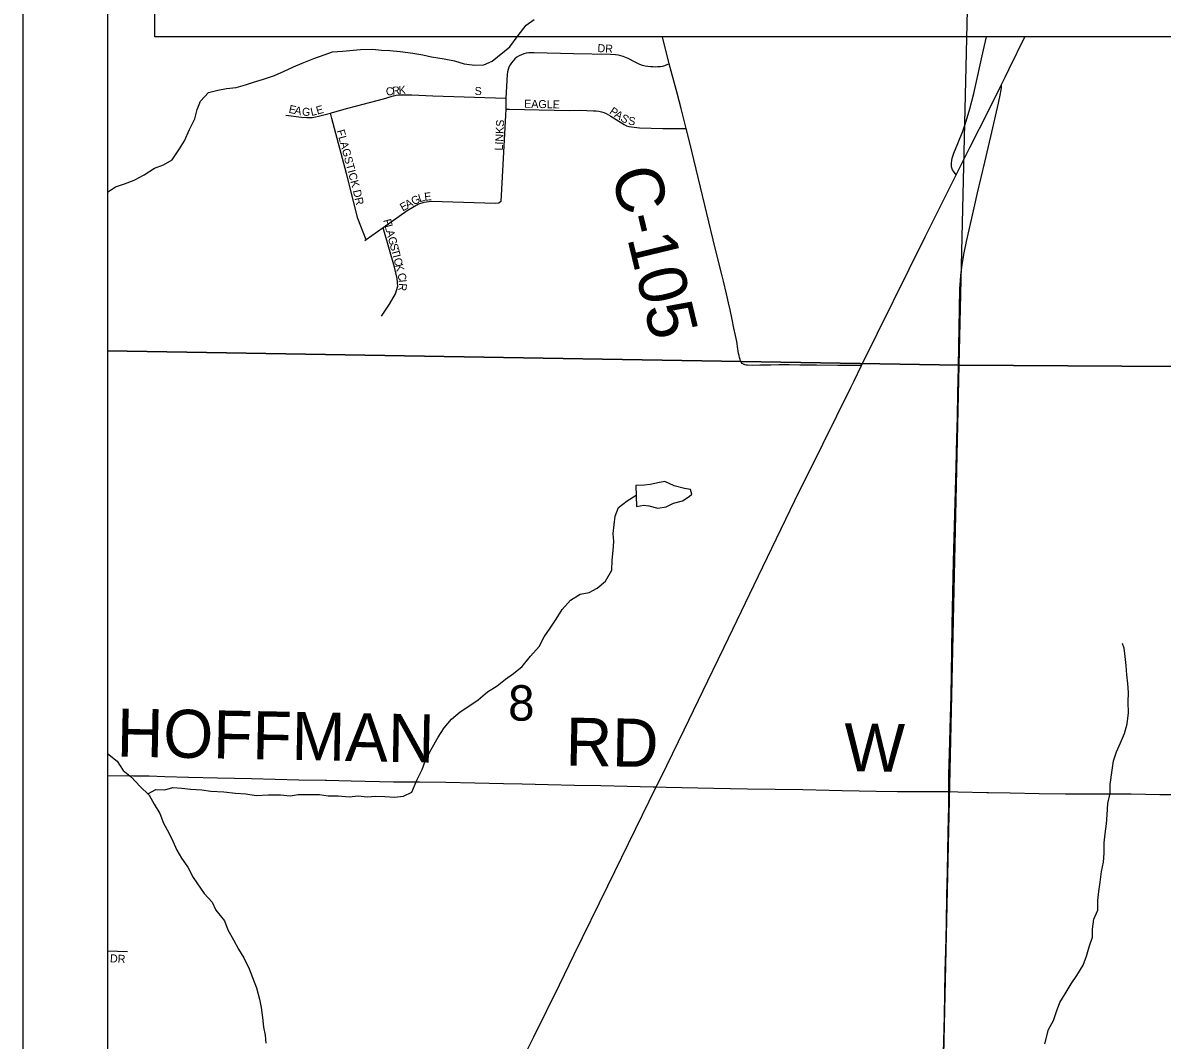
# Model space of a CAD drawing. Extents: x -97 to 34, y -21 to 22.
# Drawn here: x 3.451 to 4.799, y 15.667 to 16.869 of the extents above; entities that cross this region are included whole.
import ezdxf

# ---------------------------------------------------------------- set-up
doc = ezdxf.new("R2010")
doc.units = 0
for name, color, linetype in [('GM_X_County_Road', 7, 'Continuous'), ('GM_X_County_Road_Text', 7, 'Continuous'), ('GM_X_Minor_Lake', 7, 'Continuous'), ('GM_X_Minor_River', 7, 'Continuous'), ('GM_X_Section', 7, 'Continuous'), ('GM_X_Section_Text', 7, 'Continuous'), ('GM_X_State_Route', 7, 'Continuous'), ('GM_X_Township_Subdivision', 7, 'Continuous'), ('GM_X_Township_Subdivision_Text', 7, 'Continuous'), ('SH_Data', 7, 'Continuous'), ('SH_Text', 7, 'Continuous')]:
    doc.layers.add(name, color=color, linetype=linetype)

msp = doc.modelspace()

# ---------------------------------------------------------------- linework, layer by layer
at = {"layer": 'GM_X_County_Road'}
for points in [[(4.2162, 16.821), (4.2085, 16.8511), (4.208, 16.8527)], [(4.5557, 16.6897), (4.5525, 16.694), (4.5514, 16.6957), (4.5506, 16.6978), (4.5502, 16.6991), (4.55, 16.7006), (4.5499, 16.7021), (4.5499, 16.7036), (4.5503, 16.7065), (4.551, 16.7094), (4.5529, 16.7152), (4.5576, 16.7267), (4.5635, 16.7412), (4.5676, 16.753), (4.5719, 16.7679), (4.5764, 16.786), (4.5881, 16.8375), (4.5915, 16.8527)], [(4.2363, 16.7446), (4.2304, 16.7683), (4.2256, 16.7862), (4.2162, 16.821)], [(4.5576, 16.4315), (4.5584, 16.4622), (4.5587, 16.4871), (4.5596, 16.5306), (4.5601, 16.5554), (4.5606, 16.5648), (4.5611, 16.571), (4.5627, 16.5834), (4.5648, 16.5956), (4.5679, 16.6109), (4.5761, 16.6473), (4.5808, 16.6685), (4.5894, 16.7048), (4.5966, 16.735), (4.6055, 16.7744), (4.6082, 16.7858), (4.6086, 16.7882), (4.6089, 16.7901), (4.6091, 16.7925), (4.6092, 16.7964)], [(4.2789, 16.5703), (4.2704, 16.6029), (4.2531, 16.6752), (4.2401, 16.7293), (4.2363, 16.7446)], [(4.4438, 16.4643), (4.4385, 16.4642), (4.4323, 16.4641), (4.423, 16.4643), (4.4156, 16.4643), (4.3904, 16.4646), (4.3706, 16.4648), (4.3581, 16.465), (4.3457, 16.4649), (4.3365, 16.4648), (4.3274, 16.4647), (4.3235, 16.4646), (4.3147, 16.4643), (4.3087, 16.4645), (4.3071, 16.4647), (4.3055, 16.465), (4.3039, 16.4658), (4.3026, 16.4667), (4.3014, 16.4681), (4.3005, 16.4698), (4.2999, 16.4715), (4.2992, 16.4737), (4.2988, 16.4762), (4.2983, 16.4785), (4.2979, 16.4811), (4.2975, 16.484), (4.296, 16.4928), (4.2946, 16.4998), (4.2927, 16.5086), (4.2906, 16.5185), (4.2882, 16.5301), (4.2863, 16.5385), (4.2841, 16.5491), (4.2805, 16.5639), (4.2789, 16.5703)], [(4.547, 15.9605), (4.5471, 15.9807), (4.5476, 16.0056), (4.5489, 16.0491), (4.5496, 16.0739), (4.5505, 16.1267), (4.5507, 16.1578), (4.5517, 16.1951), (4.5526, 16.2324), (4.5557, 16.3442), (4.5565, 16.3783), (4.557, 16.4032), (4.5576, 16.4312), (4.5576, 16.4315)], [(3.5515, 15.9797), (3.5824, 15.9793)], [(3.5824, 15.9793), (3.601, 15.9791), (3.6196, 15.9785), (3.6476, 15.9776), (3.6817, 15.977), (3.7221, 15.9759), (3.7501, 15.9753), (3.778, 15.9746), (3.8091, 15.974), (3.8106, 15.974)], [(3.8106, 15.974), (3.8401, 15.9733), (3.8898, 15.9721), (3.9209, 15.972), (3.952, 15.9717), (3.9861, 15.971), (4.0202, 15.9702), (4.042, 15.9696), (4.0731, 15.969), (4.1041, 15.9683), (4.1352, 15.9676), (4.1663, 15.9669), (4.1973, 15.9663), (4.2009, 15.9662)], [(4.2009, 15.9662), (4.2127, 15.9657), (4.2313, 15.9652), (4.2686, 15.9645), (4.3089, 15.9639), (4.3741, 15.9629), (4.4052, 15.9623), (4.4207, 15.962), (4.4611, 15.9611), (4.486, 15.9606), (4.5388, 15.9608), (4.547, 15.9605)], [(4.5335, 15.2947), (4.5335, 15.2973), (4.5339, 15.3284), (4.5342, 15.3594), (4.5352, 15.3998), (4.5356, 15.4278), (4.5359, 15.4495), (4.5369, 15.493), (4.5379, 15.5396), (4.5394, 15.5986), (4.5405, 15.6514), (4.5417, 15.695), (4.5426, 15.7478), (4.5432, 15.7726), (4.5441, 15.8037), (4.5446, 15.8379), (4.5452, 15.8658), (4.546, 15.9124), (4.5468, 15.9435), (4.547, 15.959), (4.547, 15.9605)], [(4.547, 15.9605), (4.5575, 15.9601), (4.5917, 15.9595), (4.594, 15.9594)], [(4.594, 15.9594), (4.6195, 15.9589), (4.6537, 15.9584), (4.6851, 15.958), (4.7283, 15.9579), (4.7625, 15.9577), (4.7967, 15.9573), (4.8246, 15.957), (4.8495, 15.9569), (4.8619, 15.9569), (4.9054, 15.9566), (4.9458, 15.9566), (4.9862, 15.9567), (5.0235, 15.9568), (5.0577, 15.9568), (5.0918, 15.9568), (5.1291, 15.9569), (5.2006, 15.9563), (5.2565, 15.9559), (5.285, 15.9558)]]:
    msp.add_lwpolyline(points, dxfattribs=at)
at = {"layer": 'GM_X_Minor_Lake'}
for points in [[(4.1774, 16.2974), (4.1861, 16.2992), (4.1921, 16.2983), (4.2027, 16.2955), (4.2125, 16.2972), (4.2213, 16.3016), (4.2319, 16.3044), (4.2396, 16.3096), (4.243, 16.3122), (4.2412, 16.3175), (4.2341, 16.3188), (4.222, 16.322), (4.2111, 16.3272), (4.2047, 16.3261), (4.1937, 16.3237), (4.1869, 16.323), (4.1767, 16.3224)], [(4.1767, 16.3224), (4.1774, 16.2974)]]:
    msp.add_lwpolyline(points, dxfattribs=at)
at = {"layer": 'GM_X_Minor_River'}
for points in [[(3.5515, 16.6693), (3.561, 16.6754), (3.5716, 16.679), (3.5834, 16.6833), (3.5952, 16.6899), (3.6071, 16.6977), (3.6181, 16.7017), (3.628, 16.7076), (3.6369, 16.7203), (3.6428, 16.7301), (3.6487, 16.7432), (3.6549, 16.756), (3.6577, 16.767), (3.6617, 16.7768), (3.6713, 16.7872), (3.6823, 16.79), (3.6926, 16.7918), (3.7039, 16.7931), (3.7149, 16.7963), (3.7244, 16.7992), (3.7362, 16.8028), (3.7491, 16.8071), (3.7606, 16.8122), (3.7716, 16.8173), (3.7819, 16.8217), (3.7956, 16.8271), (3.8078, 16.8315), (3.818, 16.8351), (3.8298, 16.836), (3.851, 16.8379), (3.865, 16.8381), (3.8759, 16.8371), (3.8857, 16.8366), (3.8978, 16.8356), (3.9129, 16.8335), (3.9246, 16.8314), (3.9351, 16.8293), (3.9498, 16.8268), (3.9623, 16.8246), (3.9736, 16.821), (3.9864, 16.8193), (3.997, 16.8199), (4.0069, 16.8239), (4.0276, 16.841), (4.0373, 16.8544), (4.0469, 16.8668), (4.0565, 16.8734)], [(3.5992, 15.958), (3.6089, 15.963), (3.6195, 15.9628), (3.629, 15.9653), (3.6396, 15.9644), (3.6497, 15.9634), (3.6633, 15.9628), (3.6739, 15.9611), (3.6894, 15.9601), (3.703, 15.9587), (3.7154, 15.9578), (3.7275, 15.956), (3.7423, 15.9569), (3.7562, 15.9567), (3.7676, 15.9557), (3.7774, 15.9571), (3.7903, 15.9572), (3.8024, 15.957), (3.8126, 15.9557), (3.8247, 15.9555), (3.8375, 15.9545), (3.8481, 15.9555), (3.8587, 15.9545), (3.8689, 15.9551), (3.8798, 15.9549), (3.8912, 15.954), (3.9018, 15.9553), (3.9117, 15.9597), (3.9176, 15.974), (3.9238, 15.9868), (3.9274, 15.9966), (3.9344, 16.0105), (3.943, 16.0247), (3.95, 16.036), (3.9585, 16.0461), (3.9688, 16.055), (3.9791, 16.0616), (3.9902, 16.069), (4.0013, 16.0783), (4.0128, 16.0857), (4.0224, 16.0935), (4.032, 16.1001), (4.0423, 16.1083), (4.052, 16.1206), (4.0624, 16.1322), (4.0682, 16.1435), (4.0752, 16.1536), (4.0825, 16.1645), (4.0895, 16.1757), (4.0992, 16.1869), (4.111, 16.1939), (4.1213, 16.196), (4.1308, 16.2012), (4.1408, 16.2093), (4.1482, 16.2225), (4.1487, 16.2342), (4.1497, 16.2456), (4.1506, 16.2562), (4.15, 16.2657), (4.1509, 16.2759), (4.1522, 16.2861), (4.1562, 16.2963), (4.1665, 16.3044), (4.177, 16.3108)], [(4.6606, 15.6625), (4.665, 15.6794), (4.6709, 15.6899), (4.6741, 15.7005), (4.6784, 15.711), (4.6846, 15.7215), (4.6916, 15.7332), (4.6982, 15.7433), (4.706, 15.7553), (4.7099, 15.7658), (4.7131, 15.7772), (4.7167, 15.7885), (4.7169, 15.7979), (4.7186, 15.8097), (4.7233, 15.8202), (4.7231, 15.8319), (4.7244, 15.8425), (4.7261, 15.8535), (4.7275, 15.866), (4.7299, 15.8773), (4.7305, 15.8879), (4.7307, 15.9001), (4.732, 15.9106), (4.7333, 15.9224), (4.7343, 15.933), (4.7352, 15.9466), (4.7377, 15.9587), (4.7379, 15.9689), (4.7401, 15.9859), (4.7417, 15.9969), (4.7453, 16.0075), (4.75, 16.018), (4.7548, 16.0293), (4.758, 16.0406), (4.7593, 16.0535), (4.7592, 16.0664), (4.7593, 16.0777), (4.7588, 16.0883), (4.7574, 16.0986), (4.7565, 16.1096), (4.7555, 16.1202), (4.7545, 16.1301), (4.7524, 16.1355)], [(3.5515, 16.0061), (3.5518, 16.0057), (3.563, 15.9964), (3.5703, 15.9853), (3.58, 15.9775), (3.5901, 15.9671), (3.6009, 15.9563), (3.6067, 15.9456), (3.6137, 15.9345), (3.6181, 15.9234), (3.6243, 15.9116), (3.6291, 15.902), (3.6338, 15.8913), (3.6393, 15.8817), (3.6467, 15.871), (3.6529, 15.8591), (3.6662, 15.84), (3.6755, 15.8299), (3.6799, 15.8204), (3.6899, 15.8077), (3.6939, 15.797), (3.7009, 15.7852), (3.7067, 15.7741), (3.713, 15.7641), (3.7192, 15.7511), (3.7232, 15.7408), (3.7279, 15.7286), (3.7314, 15.7153), (3.7336, 15.7054), (3.7349, 15.6936), (3.7362, 15.6822), (3.7383, 15.6727), (3.7389, 15.6632)]]:
    msp.add_lwpolyline(points, dxfattribs=at)
at = {"layer": 'GM_X_Section'}
for p, q in [((3.5515, 17.0296), (3.5515, 16.4817)), ((3.5515, 16.4817), (3.5515, 15.4711))]:
    msp.add_line(p, q, dxfattribs=at)
for points in [[(3.5515, 16.4817), (4.5591, 16.4647), (4.5827, 17.473), (3.5795, 17.4795), (3.5515, 17.0296)], [(3.5515, 15.4711), (4.5367, 15.4537), (4.5591, 16.4647), (3.5515, 16.4817)]]:
    msp.add_lwpolyline(points, dxfattribs=at)
for points in [[(4.5827, 17.473), (5.5851, 17.4654), (5.5865, 16.4584), (4.5591, 16.4647)], [(4.5591, 16.4647), (5.5865, 16.4584), (5.5758, 15.4541), (4.5367, 15.4537)]]:
    msp.add_lwpolyline(points, close=True, dxfattribs=at)
at = {"layer": 'GM_X_State_Route'}
for points in [[(4.6184, 16.8152), (4.6369, 16.8527)], [(4.4345, 16.4455), (4.4438, 16.4643), (4.5189, 16.6165), (4.5557, 16.6897), (4.5719, 16.722), (4.5943, 16.7663), (4.6092, 16.7964), (4.6135, 16.8053), (4.6184, 16.8152)], [(4.0339, 15.6263), (4.0561, 15.6707), (4.0862, 15.7321), (4.1039, 15.7681), (4.1437, 15.8492), (4.1764, 15.9162), (4.2009, 15.9662), (4.2065, 15.9776), (4.2337, 16.0334), (4.262, 16.0916), (4.274, 16.1167), (4.281, 16.1313), (4.327, 16.2263), (4.3649, 16.3046), (4.398, 16.3714), (4.4309, 16.4382), (4.4345, 16.4455)]]:
    msp.add_lwpolyline(points, dxfattribs=at)
at = {"layer": 'GM_X_Township_Subdivision'}
for points in [[(4.2162, 16.821), (4.2107, 16.8186), (4.2082, 16.8179), (4.2057, 16.8175), (4.2028, 16.8172), (4.2002, 16.8171), (4.197, 16.8172), (4.1939, 16.8175), (4.1907, 16.8178), (4.1876, 16.8183), (4.1845, 16.8191), (4.1815, 16.8201), (4.1757, 16.8228), (4.1674, 16.8271), (4.1617, 16.8295), (4.1588, 16.8305), (4.1558, 16.8311), (4.1528, 16.8316), (4.1467, 16.832), (4.1031, 16.8327), (4.0562, 16.8341), (4.0501, 16.8339), (4.0471, 16.8335), (4.0441, 16.8327), (4.0413, 16.8317), (4.0386, 16.8303), (4.036, 16.8287), (4.0337, 16.8268), (4.0316, 16.8246), (4.0297, 16.8222), (4.028, 16.8197), (4.0266, 16.817), (4.0255, 16.8142), (4.0247, 16.8113), (4.0243, 16.8083), (4.0229, 16.7804)], [(3.8541, 16.7733), (3.8781, 16.7797), (3.8871, 16.7823), (3.8898, 16.7831), (3.8931, 16.7838), (3.8962, 16.7842), (3.8991, 16.7844), (3.9015, 16.7843), (3.9118, 16.7841), (3.9367, 16.7832), (4.0229, 16.7804)], [(3.8155, 16.7628), (3.8179, 16.7634), (3.8359, 16.7685), (3.8541, 16.7733)], [(4.0229, 16.7804), (4.0229, 16.7727), (4.0227, 16.7673)], [(3.7627, 16.7603), (3.7812, 16.7579), (3.7874, 16.7574), (3.7906, 16.7574), (3.7936, 16.7576), (3.7998, 16.7587), (3.8155, 16.7628)], [(3.8575, 16.6129), (3.8575, 16.613), (3.8477, 16.638), (3.8344, 16.6913), (3.8296, 16.709), (3.8172, 16.7563), (3.8155, 16.7628)], [(4.0227, 16.7673), (4.0224, 16.7601), (4.017, 16.6582), (4.0145, 16.6563), (4.0107, 16.656), (3.9348, 16.6582), (3.9257, 16.657), (3.9196, 16.655), (3.9061, 16.6471), (3.8779, 16.6272)], [(4.0227, 16.7673), (4.0272, 16.7673), (4.0799, 16.7662), (4.0985, 16.7659), (4.111, 16.766), (4.1265, 16.7655), (4.1296, 16.7653), (4.1328, 16.7649), (4.1359, 16.7643), (4.1389, 16.7633), (4.1415, 16.7622), (4.1469, 16.7589), (4.1628, 16.7492), (4.1655, 16.7478), (4.1685, 16.7469), (4.1715, 16.7463), (4.1808, 16.7454), (4.2087, 16.7445), (4.2272, 16.7444), (4.2303, 16.7445), (4.2363, 16.7446)], [(3.8779, 16.6272), (3.8575, 16.6129)], [(3.8757, 16.5227), (3.8854, 16.5368), (3.8924, 16.549), (3.895, 16.5581), (3.8944, 16.5672), (3.8913, 16.5805), (3.8779, 16.6272)], [(3.8575, 16.6129), (3.8559, 16.6118)], [(3.5515, 15.7722), (3.5752, 15.7714)]]:
    msp.add_lwpolyline(points, dxfattribs=at)
at = {"layer": 'SH_Data'}
for p, q in [((3.4515, 20.9177), (3.4515, 13.9177)), ((3.5515, 20.8177), (3.5515, 14.0177))]:
    msp.add_line(p, q, dxfattribs=at)
at = {"layer": 'SH_Text'}
msp.add_lwpolyline([(3.6076, 17.3534), (5.5255, 17.3534), (5.5255, 16.8527), (3.6076, 16.8527)], close=True, dxfattribs=at)

# ---------------------------------------------------------------- texts
at = {"layer": 'GM_X_County_Road_Text'}
for s, height, rotation, p in [('C-105', 0.05682, 283.5704, (4.1475, 16.6928)), ('HOFFMAN', 0.05682, 358.8819, (3.5623, 16.0021)), ('RD', 0.05682, 359.0267, (4.0933, 15.9913)), ('W', 0.0568, 359.2752, (4.4229, 15.9846))]:
    msp.add_text(s, height=height, rotation=rotation, dxfattribs=at).set_placement(p)
at = {"layer": 'GM_X_Section_Text'}
msp.add_text('8', height=0.0419, rotation=0, dxfattribs=at).set_placement((4.0256, 16.0444))
at = {"layer": 'GM_X_Township_Subdivision_Text'}
for s, rotation, p in [('DR', 356.989, (4.1311, 16.8349)), ('K', 4.4624, (3.8964, 16.785)), ('C', 7.0347, (3.8816, 16.7832)), ('R', 7.0106, (3.889, 16.7841)), ('S', 0, (3.986, 16.7841)), ('E', 348.2774, (3.7655, 16.7632)), ('A', 348.3022, (3.7721, 16.7618)), ('G', 354.0561, (3.7813, 16.76)), ('L', 12.5402, (3.7929, 16.7593)), ('E', 15.0648, (3.7998, 16.7609)), ('EAGLE', 358.7554, (4.0444, 16.7691)), ('P', 325.3325, (4.1446, 16.7628)), ('LINKS', 87.2035, (4.0192, 16.7182)), ('A', 327.5811, (4.1505, 16.7588)), ('S', 328.9707, (4.1577, 16.7542)), ('S', 350.352, (4.167, 16.7494)), ('FLAGSTICK', 285.1226, (3.8227, 16.7419)), ('DR', 282.5327, (3.8419, 16.671)), ('A', 29.4304, (3.9067, 16.6496)), ('G', 26.8485, (3.9138, 16.6536)), ('L', 16.6208, (3.9208, 16.6572)), ('E', 5.4714, (3.9268, 16.659)), ('E', 29.45, (3.9009, 16.6463)), ('F', 284.891, (3.8777, 16.6361)), ('L', 284.888, (3.8794, 16.6297)), ('A', 284.9004, (3.8811, 16.6232)), ('G', 284.8737, (3.8833, 16.6152)), ('S', 284.9126, (3.8854, 16.6071)), ('T', 284.891, (3.8871, 16.6007)), ('I', 284.8738, (3.8889, 16.5942)), ('C', 284.9033, (3.8899, 16.5902)), ('K', 284.9004, (3.8918, 16.5829)), ('C', 282.2101, (3.8946, 16.5726)), ('R', 264.5528, (3.8966, 16.5619)), ('I', 275.6932, (3.8961, 16.5655)), ('DR', 356.989, (3.5544, 15.7588))]:
    msp.add_text(s, height=0.00947, rotation=rotation, dxfattribs=at).set_placement(p)

doc.saveas('drawing.dxf')
